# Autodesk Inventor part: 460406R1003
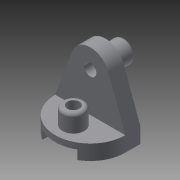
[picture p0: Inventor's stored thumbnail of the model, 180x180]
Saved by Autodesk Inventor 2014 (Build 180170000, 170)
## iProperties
Created: 2016-04
Part Number: 460406R1003
Material: 일반
Document SubType Name: Modeling
Designer: USER
Density: 1 g/cm^3
Appearance: 기본값
Author: USER
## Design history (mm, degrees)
sketch "스케치1"
  geometry: L1 (0, 0)-(116, 0); L2 (116, 0)-(116, -25); L3 (116, -25)-(0, -25); L4 (0, -25)-(0, 0); A1 r 58 centre (58, -25) between (0, -25) and (116, -25); 1 further point
  constraints: 8 end point, 2 parallel, 2 point on circle, 1 centre point, 1 coincident, 1 horizontal, 1 midpoint, 1 perpendicular
  dimensions: "d0" = 25 distance between parallel lines of L3 L1; "d1" = 58 radius of A1
extrude "돌출1" new body sketch "스케치1" distance "d2" = 25; taper "d3" = 0 deg
extrude "돌출2" join sketch "스케치1" distance "d4" = 122; taper "d5" = 0 deg
sketch "스케치2"
  geometry: L1 (116, 0)-(0, 0) reference; L2 (116, 0)-(116, 97) reference; L3 (0, 97)-(116, 97) reference; L4 (0, 0)-(0, 97) reference; L5 (0, 0)-(27.967, 76.045); L6 (88.033, 76.045)-(116, 0); L7 (116, 0)-(0, 0) reference; A1 r 32 centre (58, 65) between (88.033, 76.045) and (27.967, 76.045); 2 further points
  constraints: 4 end point, 3 tangent, 2 point on circle, 1 centre point, 1 midpoint, 1 vertical alignment
  dimensions: "d6" = 32 radius of A1
extrude "돌출3" cut sketch "스케치2" stored distance "d7" = 122; taper "d8" = 0 deg
sketch "스케치3"
  geometry: L1 (116, 0)-(116, -25) reference; L2 (116, 0)-(0, 0) reference; L3 (87, 0)-(29, 0); L4 (29, 0)-(29, -15); L5 (29, -15)-(87, -15); L6 (87, -15)-(87, 0)
  constraints: 8 end point, 2 parallel, 1 horizontal, 1 perpendicular, 1 point on line
  dimensions: "d9" = 29 distance between parallel lines of L6 L1; "d10" = 58 distance between parallel lines of L4 L6; "d11" = 15 distance between parallel lines of L5 L2
extrude "돌출4" cut sketch "스케치3" stored distance "d12" = 122; taper "d13" = 0 deg
sketch "스케치4"
  geometry: C1 r 18 at (58, 65); C2 r 10 at (58, 65); A1 r 32 centre (58, 65) between (88.033, 76.045) and (27.967, 76.045) reference; 1 further point
  constraints: 2 centre point, 2 coincident
  dimensions: "d14" = 18 radius of C1; "d15" = 10 radius of C2
extrude "돌출5" join sketch "스케치4" distance "d16" = 57; taper "d17" = 0 deg
extrude "돌출6" cut sketch "스케치4" distance "d18" = 57; taper "d19" = 0 deg
sketch "스케치5"
  geometry: L1 (116, -25)-(0, -25) reference; L2 (88.033, 0)-(27.967, 0) reference; L3 (88.033, 0)-(116, 0) reference; C1 r 10 at (58, -53); C2 r 18 at (58, -53); A1 r 58 centre (58, -25) between (0, -25) and (116, -25) reference; 3 further points
  constraints: 2 centre point, 2 vertical alignment, 1 coincident, 1 midpoint, 1 point on circle
  dimensions: "d20" = 53 distance from line of C1.centre L2; "d21" = 10 radius of C1; "d22" = 18 radius of C2
extrude "돌출7" join sketch "스케치5" distance "d23" = 28; taper "d24" = 0 deg
extrude "돌출8" cut sketch "스케치5" stored distance "d25" = 28; taper "d26" = 0 deg
fillet "모깎기1" dims "d27" = 5
node "솔리드1"
